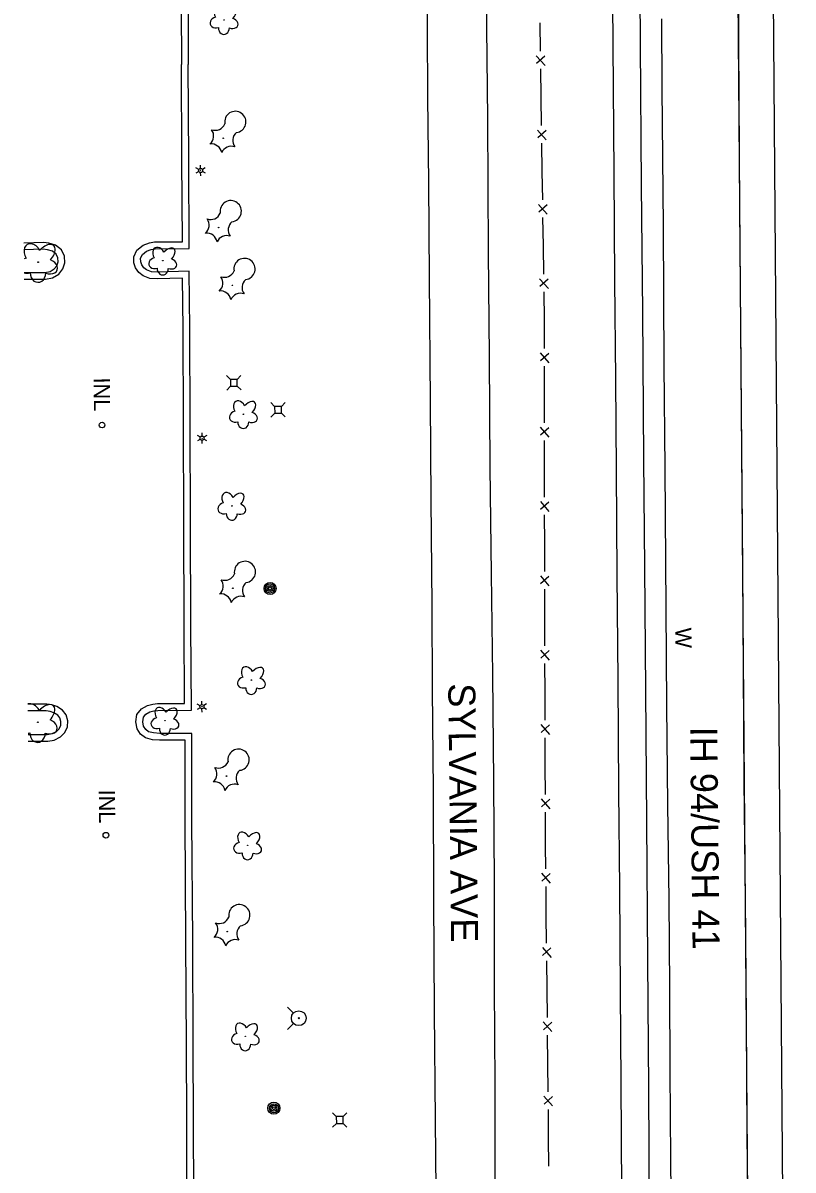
# Model space of a CAD drawing. Extents: x 588843 to 2552415, y 180129 to 269402.
# Drawn here: x 593752.2 to 594037.2, y 180752.2 to 181176.7 of the extents above; entities that cross this region are included whole.
import ezdxf

# ---------------------------------------------------------------- set-up
doc = ezdxf.new("R2010")
doc.units = 0
for name, color, linetype in [('Default', 7, 'Continuous'), ('E_DRN', 7, 'Continuous'), ('E_DRN_Text', 7, 'Continuous'), ('E_DWY', 7, 'Continuous'), ('E_FEN_P', 7, 'Continuous'), ('E_LAND_Vegetation', 7, 'Continuous'), ('E_LTG', 7, 'Continuous'), ('E_MISCPROP', 7, 'Continuous'), ('E_RDWY', 7, 'Continuous'), ('E_RDWY_Gravel', 7, 'Continuous'), ('E_RDWY_Text', 7, 'Continuous'), ('E_UTL_AG_Bold', 7, 'Continuous'), ('E_UTL_WHydrant', 7, 'Continuous'), ('E_WAL', 7, 'Continuous'), ('E_WAL_Text', 7, 'Continuous'), ('P_RDWY_PavtEdge', 7, 'Continuous'), ('P_TC_BarrierConc', 7, 'Continuous')]:
    doc.layers.add(name, color=color, linetype=linetype)

# ---------------------------------------------------------------- blocks, each defined once
blk = doc.blocks.new('W_3')
at = {"layer": 'E_WAL_Text'}
blk.add_text('W', height=12, dxfattribs=at).set_placement((-4.46, -6))
blk = doc.blocks.new('INLT_3')
at = {"layer": 'E_DRN_Text'}
blk.add_text('INL', height=12, dxfattribs=at).set_placement((-11.03, -6))
blk = doc.blocks.new('PED')
at = {"layer": 'Default'}
for p, q in [((-2.5, 2.5), (-5.33, 5.33)), ((2.5, 2.5), (5.33, 5.33)), ((-2.5, -2.5), (-5.33, -5.33)), ((2.5, -2.5), (5.33, -5.33))]:
    blk.add_line(p, q, dxfattribs=at)
blk.add_lwpolyline([(-2.5, -2.5), (2.5, -2.5), (2.5, 2.5), (-2.5, 2.5)], close=True, dxfattribs=at)
blk = doc.blocks.new('LPOL')
at = {"layer": 'Default'}
for p, q in [((-4, 0), (-1.5, 0)), ((-0.75, 1.3), (-2, 3.46)), ((0.75, 1.3), (2, 3.46)), ((1.5, 0), (4, 0)), ((-2, -3.46), (-0.75, -1.3)), ((2, -3.46), (0.75, -1.3))]:
    blk.add_line(p, q, dxfattribs=at)
for radius in [1.5, 1.5, 1.5, 0.125]:
    blk.add_circle((0, 0), radius, dxfattribs=at)
blk = doc.blocks.new('POLE')
at = {"layer": 'Default'}
for radius in [4.46, 3.35, 2.23, 1.12]:
    blk.add_circle((0, 0), radius, dxfattribs=at)
blk = doc.blocks.new('HYD')
at = {"layer": 'Default'}
for p, q in [((-3.84, 3.84), (-8.32, 8.32)), ((3.84, 3.84), (8.32, 8.32))]:
    blk.add_line(p, q, dxfattribs=at)
for radius in [5.48, 0.42]:
    blk.add_circle((0, 0), radius, dxfattribs=at)
blk = doc.blocks.new('CTRE')
at = {"layer": 'Default'}
blk.add_circle((0, 0), 0.223, dxfattribs=at)
for centre, start, end in [((-11.97, 8.96), 280.2067, 5.97162), ((1.81, 14.92), 220.21132, 305.97623), ((13.83, 5.89), 160.21133, 245.97624), ((-13.83, -5.9), 340.21132, 65.97623), ((-1.81, -14.93), 40.21133, 125.97624), ((12.03, -9.04), 185.92721, 100.25111)]:
    blk.add_arc(centre, 7.87, start, end, dxfattribs=at)
blk = doc.blocks.new('DTRE')
at = {"layer": 'Default'}
blk.add_circle((-0.18, 0), 0.183, dxfattribs=at)
for centre, major_axis, ratio in [((-1.87, 5.32), (1.36, -4.98), 0.782863), ((-5.87, 0.15), (4.93, -0.12), 0.832022), ((4.06, 2.74), (-5.27, -2.93), 0.691916), ((-2.49, -5.24), (1.8, 4.86), 0.716896), ((3.54, -3.71), (-5.01, 4.58), 0.560249)]:
    blk.add_ellipse(centre, major_axis=major_axis, ratio=ratio, start_param=1.570796, end_param=4.712389, dxfattribs=at)

msp = doc.modelspace()

# ---------------------------------------------------------------- linework, layer by layer
at = {"layer": 'E_DRN'}
for centre, radius in [((593781.47, 181027.91), 1.04), ((593782.92, 180876.11), 1.06)]:
    msp.add_circle(centre, radius, dxfattribs=at)
at = {"layer": 'E_DWY'}
for points in [[(593810.71, 181224.63), (593810.79, 181182.72), (593810.87, 181161.35)], [(593813.21, 181224.64), (593813.29, 181182.72), (593813.37, 181161.36)], [(593811.46, 181063.67), (593811.28, 181082.3), (593801.88, 181082), (593799.2, 181082.18), (593796.74, 181083.07), (593795.04, 181084.34), (593793.91, 181086.07), (593793.29, 181087.88), (593793.22, 181090.17), (593794.39, 181092.68), (593796.67, 181094.49), (593799.03, 181095.31), (593800.91, 181095.66), (593811.2, 181095.72), (593811.04, 181126.11), (593810.87, 181161.35)], [(593813.96, 181063.69), (593813.76, 181084.88), (593801.93, 181084.5), (593799.72, 181084.65), (593797.94, 181085.3), (593796.89, 181086.08), (593796.17, 181087.18), (593795.78, 181088.33), (593795.74, 181089.65), (593796.41, 181091.08), (593797.9, 181092.27), (593799.67, 181092.89), (593801.15, 181093.16), (593813.71, 181093.23), (593813.54, 181126.12), (593813.37, 181161.36)], [(593752.66, 181081.87), (593760.61, 181081.87), (593763.15, 181082.39), (593765.52, 181083.76), (593766.97, 181085.69), (593767.7, 181087.9), (593767.64, 181090.4), (593766.5, 181092.75), (593764.31, 181094.53), (593761.83, 181095.17), (593759.84, 181095.45), (593752.55, 181095.23)], [(593752.64, 181084.37), (593760.36, 181084.37), (593762.25, 181084.75), (593763.82, 181085.67), (593764.72, 181086.86), (593765.19, 181088.27), (593765.15, 181089.8), (593764.5, 181091.16), (593763.16, 181092.24), (593761.34, 181092.71), (593759.7, 181092.94), (593752.57, 181092.73)], [(593812.69, 180798.25), (593812.52, 180837.05), (593812.26, 180881.68), (593812.2, 180911.3), (593802.73, 180911.23), (593800.09, 180911.47), (593797.59, 180912.12), (593795.76, 180913.49), (593794.45, 180915.53), (593793.99, 180918.02), (593794.41, 180920.81), (593796.04, 180922.84), (593798.26, 180924.17), (593800.29, 180924.62), (593801.94, 180924.8), (593812.04, 180924.84), (593811.86, 180953.69), (593811.74, 180991.64), (593811.57, 181028.59), (593811.46, 181063.69)], [(593815.19, 180798.26), (593815.02, 180837.07), (593814.76, 180881.69), (593814.69, 180913.81), (593802.84, 180913.73), (593800.52, 180913.94), (593798.7, 180914.41), (593797.62, 180915.22), (593796.82, 180916.47), (593796.52, 180918.06), (593796.78, 180919.77), (593797.71, 180920.93), (593799.2, 180921.82), (593800.7, 180922.15), (593802.09, 180922.3), (593814.56, 180922.35), (593814.36, 180953.71), (593814.24, 180991.65), (593814.07, 181028.6), (593813.96, 181063.69)], [(593754.1, 180910.88), (593761.39, 180910.87), (593763.8, 180911.34), (593766.11, 180912.51), (593767.66, 180914.1), (593768.64, 180916.23), (593768.78, 180918.45), (593768.14, 180920.68), (593766.83, 180922.39), (593764.76, 180923.7), (593762.86, 180924.32), (593761, 180924.6), (593759.93, 180924.66), (593753.99, 180924.61)], [(593754.08, 180913.38), (593761.15, 180913.37), (593762.98, 180913.72), (593764.61, 180914.55), (593765.57, 180915.54), (593766.18, 180916.85), (593766.26, 180918.17), (593765.86, 180919.53), (593765.11, 180920.52), (593763.69, 180921.42), (593762.28, 180921.88), (593760.76, 180922.11), (593759.87, 180922.16), (593754.01, 180922.11)], [(593813.57, 180633.49), (593813.49, 180662.87), (593813.22, 180700.46), (593813.03, 180731.17), (593802.98, 180731.09), (593800.07, 180731.47), (593797.84, 180732.65), (593796.26, 180734.28), (593795.24, 180736.1), (593794.94, 180738.32), (593795.31, 180740.37), (593796.36, 180742.18), (593798.59, 180743.87), (593800.58, 180744.5), (593802.72, 180744.7), (593804.49, 180744.8), (593812.91, 180744.81), (593812.87, 180770.28), (593812.69, 180798.25)], [(593816.07, 180633.5), (593815.99, 180662.88), (593815.72, 180700.48), (593815.52, 180733.69), (593803.13, 180733.59), (593800.84, 180733.89), (593799.36, 180734.68), (593798.29, 180735.78), (593797.66, 180736.91), (593797.47, 180738.27), (593797.7, 180739.5), (593798.27, 180740.49), (593799.76, 180741.61), (593801.09, 180742.03), (593802.91, 180742.21), (593804.56, 180742.3), (593815.42, 180742.31), (593815.37, 180770.29), (593815.19, 180798.26)]]:
    msp.add_lwpolyline(points, dxfattribs=at)
at = {"layer": 'E_FEN_P'}
for p, q in [((593942.16, 181164.58), (593945.4, 181160.97)), ((593945.34, 181164.46), (593942.26, 181161.66)), ((593942.57, 181137.08), (593945.81, 181133.47)), ((593945.76, 181136.96), (593942.68, 181134.16)), ((593942.98, 181109.58), (593946.22, 181105.97)), ((593946.17, 181109.46), (593943.09, 181106.66)), ((593943.39, 181082.07), (593946.63, 181078.46)), ((593946.58, 181081.95), (593943.5, 181079.16)), ((593943.64, 181054.59), (593946.82, 181050.94)), ((593946.82, 181054.43), (593943.7, 181051.67)), ((593943.65, 181027.09), (593946.83, 181023.43)), ((593946.83, 181026.92), (593943.71, 181024.17)), ((593943.66, 180999.58), (593946.85, 180995.92)), ((593946.84, 180999.41), (593943.73, 180996.66)), ((593943.67, 180972.07), (593946.86, 180968.42)), ((593946.86, 180971.91), (593943.74, 180969.16)), ((593943.76, 180944.56), (593946.96, 180940.92)), ((593946.94, 180944.41), (593943.84, 180941.65)), ((593943.86, 180917.06), (593947.05, 180913.41)), ((593947.04, 180916.9), (593943.93, 180914.14)), ((593943.95, 180889.55), (593947.15, 180885.91)), ((593947.14, 180889.4), (593944.03, 180886.63)), ((593944.12, 180862.04), (593947.35, 180858.41)), ((593947.31, 180861.91), (593944.22, 180859.12)), ((593944.41, 180834.53), (593947.63, 180830.91)), ((593947.59, 180834.4), (593944.5, 180831.62)), ((593944.69, 180807.03), (593947.92, 180803.41)), ((593947.88, 180806.9), (593944.79, 180804.11)), ((593944.98, 180779.53), (593948.2, 180775.9)), ((593948.16, 180779.39), (593945.07, 180776.61))]:
    msp.add_line(p, q, dxfattribs=at)
for points in [[(593943.44, 181176.72), (593943.6, 181166.22)], [(593943.7, 181159.72), (593943.86, 181149.22)], [(593943.86, 181149.22), (593944.01, 181138.72)], [(593944.11, 181132.22), (593944.27, 181121.72)], [(593944.27, 181121.72), (593944.43, 181111.21)], [(593944.52, 181104.71), (593944.68, 181094.21)], [(593944.68, 181094.21), (593944.84, 181083.71)], [(593944.94, 181077.21), (593945.09, 181066.71)], [(593945.09, 181066.71), (593945.1, 181066.15), (593945.11, 181056.21)], [(593945.11, 181049.71), (593945.11, 181039.21)], [(593945.11, 181039.21), (593945.12, 181028.7)], [(593945.12, 181022.2), (593945.13, 181011.7)], [(593945.13, 181011.7), (593945.13, 181001.2)], [(593945.13, 180994.7), (593945.14, 180984.19)], [(593945.14, 180984.19), (593945.14, 180973.69)], [(593945.15, 180967.19), (593945.19, 180956.69)], [(593945.19, 180956.69), (593945.22, 180946.19)], [(593945.25, 180939.69), (593945.28, 180929.18)], [(593945.28, 180929.18), (593945.32, 180918.68)], [(593945.34, 180912.18), (593945.38, 180901.68)], [(593945.38, 180901.68), (593945.42, 180891.18)], [(593945.44, 180884.67), (593945.48, 180874.17)], [(593945.48, 180874.17), (593945.49, 180872.48), (593945.58, 180863.67)], [(593945.64, 180857.17), (593945.75, 180846.67)], [(593945.75, 180846.67), (593945.86, 180836.17)], [(593945.93, 180829.67), (593946.04, 180819.16)], [(593946.04, 180819.16), (593946.15, 180808.66)], [(593946.21, 180802.16), (593946.32, 180791.66)], [(593946.32, 180791.66), (593946.43, 180781.16)], [(593946.5, 180774.66), (593946.58, 180764.16)], [(593946.58, 180764.16), (593946.67, 180753.65)]]:
    msp.add_lwpolyline(points, dxfattribs=at)
at = {"layer": 'E_LAND_Vegetation'}
for centre in [(593757.84, 181088.16), (593757.7, 180917.91)]:
    msp.add_circle(centre, 0.128, dxfattribs=at)
for centre, major_axis, ratio, start_param, end_param in [((593755.9, 181091.11), (2.08, -3.67), 0.691916, 1.570796, 4.712389), ((593760.41, 181090.79), (-3.18, -3.53), 0.560249, 1.570796, 4.712389), ((593754.12, 181086.95), (3.48, 0.98), 0.782863, 1.570796, 1.794819), ((593761.52, 181086.57), (-3.41, 1.23), 0.716896, 1.570796, 4.712389), ((593754.12, 181086.95), (3.48, 0.98), 0.782863, 4.068442, 4.712389), ((593757.76, 181084.18), (0.06, 3.45), 0.832022, 1.570796, 4.712389), ((593755.76, 180920.86), (2.08, -3.67), 0.691916, 1.570796, 3.025697), ((593760.27, 180920.54), (-3.18, -3.53), 0.560249, 1.570796, 4.712389), ((593761.38, 180916.32), (-3.41, 1.23), 0.716896, 1.570796, 4.712389), ((593753.98, 180916.7), (3.48, 0.98), 0.782863, 4.522859, 4.712389), ((593757.62, 180913.93), (0.06, 3.45), 0.832022, 1.570796, 4.712389)]:
    msp.add_ellipse(centre, major_axis=major_axis, ratio=ratio, start_param=start_param, end_param=end_param, dxfattribs=at)
at = {"layer": 'E_RDWY'}
for points in [[(593920.04, 181747.12), (593920.2, 181707.24), (593920.49, 181659.97), (593920.92, 181589.62), (593921.33, 181527.56), (593921.83, 181466.82), (593922.3, 181401.73), (593922.65, 181362.99), (593923.47, 181293.57), (593923.63, 181239.18), (593923.73, 181174.95)], [(593901.88, 181174.73), (593901.67, 181219.23), (593901.26, 181282.13), (593900.88, 181335.13), (593900.51, 181390.23), (593900.19, 181443.49), (593899.68, 181492.3)], [(593980.74, 181168.67), (593980.32, 181226.89), (593979.91, 181300.34), (593979.4, 181359.92), (593978.78, 181425.4), (593978.42, 181468.6)], [(594014.75, 181468.89), (594014.96, 181435.94), (594015.49, 181369.77), (594016.03, 181302.52), (594016.63, 181235.11), (594016.95, 181169.03)], [(593907.17, 180543.98), (593906.94, 180581.8), (593906.68, 180617.44), (593906.38, 180657.53), (593906.05, 180697.51), (593905.29, 180731.59), (593904.83, 180770.62), (593904.54, 180810.93), (593904.31, 180853.03), (593904.12, 180892.61), (593903.81, 180930.07), (593903.6, 180961.11), (593903.25, 181000.18), (593903.04, 181036.62), (593902.61, 181082.22), (593902.42, 181117.68), (593901.99, 181149.13), (593901.88, 181174.73)], [(593923.73, 181174.95), (593924.05, 181141.24), (593924.35, 181091.92), (593924.71, 181053.29), (593924.99, 181012.18), (593925.48, 180972.85), (593925.93, 180935.38), (593926.35, 180896.28), (593926.53, 180858.01), (593926.57, 180820.08), (593926.78, 180784.07), (593926.85, 180743.7), (593927.25, 180705.65), (593927.75, 180671.1), (593928.23, 180633.7), (593928.33, 180601.97), (593928.89, 180545.4)], [(593981.97, 181015.32), (593981.57, 181069.65), (593981.06, 181116.55), (593980.74, 181168.67)], [(594016.95, 181169.03), (594017.4, 181108.37), (594017.76, 181064.3), (594018.06, 181018.76), (594018.42, 180975.19), (594018.74, 180936.8), (594018.97, 180896.15), (594019.43, 180852.87), (594019.84, 180808.54), (594020.11, 180765.32), (594020.56, 180721.75), (594021.01, 180674.24), (594021.29, 180627.41), (594021.63, 180584.34), (594021.9, 180542.52)], [(593985.6, 180542.06), (593985.19, 180589.94), (593984.81, 180641.08), (593984.42, 180689.85), (593984.11, 180735.89), (593983.76, 180782.32), (593983.4, 180829.82), (593983.09, 180881.18), (593982.67, 180929.66), (593982.27, 180975.15), (593981.97, 181015.32)]]:
    msp.add_lwpolyline(points, dxfattribs=at)
at = {"layer": 'E_RDWY_Gravel'}
for points in [[(593970.56, 181168.65), (593970.18, 181216.41), (593969.85, 181261.33), (593969.51, 181311.1), (593969.08, 181365.61), (593968.73, 181414.57), (593968.24, 181467.03), (593968.23, 181468.52)], [(593975.39, 180542.38), (593975.09, 180581.82), (593974.82, 180627.24), (593974.56, 180660.66), (593974.2, 180701.9), (593973.87, 180744.15), (593973.52, 180784.68), (593973.27, 180818.19), (593973.12, 180856.37), (593972.76, 180892.41), (593972.4, 180933.54), (593972.11, 180972.31), (593971.79, 181011.12), (593971.57, 181044.83), (593971.22, 181081.43), (593970.98, 181121.11), (593970.56, 181168.65)]]:
    msp.add_lwpolyline(points, dxfattribs=at)
at = {"layer": 'E_WAL'}
msp.add_lwpolyline([(593992.23, 180730.86), (593991.91, 180756.16), (593991.71, 180788.82), (593991.56, 180819.79), (593991.27, 180852.18), (593990.87, 180887.4), (593990.46, 180923.97), (593990.19, 180960.09), (593989.86, 181011.84), (593989.42, 181050.09), (593989.18, 181101.54), (593988.72, 181152.4), (593988.62, 181178.23)], dxfattribs=at)
at = {"layer": 'P_RDWY_PavtEdge'}
msp.add_line((594024.17, 180268.93), (594014.69, 181468.89), dxfattribs=at)
at = {"layer": 'P_TC_BarrierConc'}
msp.add_line((594037.17, 180269.03), (594027.69, 181468.99), dxfattribs=at)

# ---------------------------------------------------------------- block references
at = {"layer": 'E_DRN_Text', "xscale": 0.49999999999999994, "yscale": 0.49999999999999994, "rotation": -89.5545646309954}
for p in [(593781.42, 181039.99), (593783.32, 180887.47)]:
    msp.add_blockref('INLT_3', p, dxfattribs=at)
at = {"layer": 'E_LAND_Vegetation'}
for name, p, xscale, yscale, rotation in [('DTRE', (593826.65, 181177.88), 0.5000000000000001, 0.5, 90.08344940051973), ('CTRE', (593826.32, 181134.03), 0.49999999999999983, 0.4999999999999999, 90.44543536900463), ('CTRE', (593824.63, 181100.99), 0.49999999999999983, 0.4999999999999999, 90.44543536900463), ('DTRE', (593803.97, 181088.84), 0.49999999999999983, 0.4999999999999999, 90.44543536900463), ('CTRE', (593829.72, 181079.62), 0.49999999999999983, 0.4999999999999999, 90.44543536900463), ('DTRE', (593833.81, 181032.02), 0.49999999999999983, 0.4999999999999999, 90.44543536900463), ('DTRE', (593829.53, 180998.08), 0.49999999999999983, 0.4999999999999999, 90.44543536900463), ('CTRE', (593829.88, 180967.49), 0.49999999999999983, 0.4999999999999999, 90.44543536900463), ('DTRE', (593836.77, 180933.61), 0.49999999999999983, 0.4999999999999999, 90.44543536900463), ('DTRE', (593804.78, 180918.57), 0.49999999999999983, 0.4999999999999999, 90.44543536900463), ('CTRE', (593827.52, 180897.99), 0.49999999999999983, 0.4999999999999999, 90.44543536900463), ('DTRE', (593835.37, 180872.45), 0.49999999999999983, 0.4999999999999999, 90.44543536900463), ('CTRE', (593827.82, 180840.45), 0.49999999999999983, 0.4999999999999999, 90.44543536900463), ('DTRE', (593834.52, 180801.75), 0.49999999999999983, 0.4999999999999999, 90.44543536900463)]:
    msp.add_blockref(name, p, dxfattribs=dict(at, xscale=xscale, yscale=yscale, rotation=rotation))
at = {"layer": 'E_LTG', "xscale": 0.49999999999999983, "yscale": 0.4999999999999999, "rotation": 90.44543536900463}
for p in [(593817.96, 181122.12), (593818.5, 181023.04), (593818.45, 180923.68)]:
    msp.add_blockref('LPOL', p, dxfattribs=at)
at = {"layer": 'E_MISCPROP', "xscale": 0.49999999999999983, "yscale": 0.4999999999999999, "rotation": 90.44543536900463}
for p in [(593843.65, 180967.42), (593845.06, 180775.08)]:
    msp.add_blockref('POLE', p, dxfattribs=at)
at = {"layer": 'E_UTL_AG_Bold', "xscale": 0.49999999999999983, "yscale": 0.4999999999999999, "rotation": 90.44543536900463}
for p in [(593830.24, 181043.55), (593846.6, 181033.57), (593869.43, 180770.71)]:
    msp.add_blockref('PED', p, dxfattribs=at)
at = {"layer": 'E_UTL_WHydrant', "xscale": 0.49999999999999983, "yscale": 0.4999999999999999, "rotation": 90.44543536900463}
msp.add_blockref('HYD', (593854.27, 180808.39), dxfattribs=at)
at = {"layer": 'E_WAL_Text', "xscale": 0.49999999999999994, "yscale": 0.49999999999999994, "rotation": -89.5545646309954}
msp.add_blockref('W_3', (593996.6, 180950.73), dxfattribs=at)

# ---------------------------------------------------------------- texts
at = {"layer": 'E_RDWY_Text'}
for s, p in [('SYLVANIA AVE', (593909.57, 180932.29)), ('IH 94/USH 41', (593999.09, 180916.22))]:
    msp.add_text(s, height=10, rotation=270.6378, dxfattribs=at).set_placement(p)

doc.saveas('drawing.dxf')
